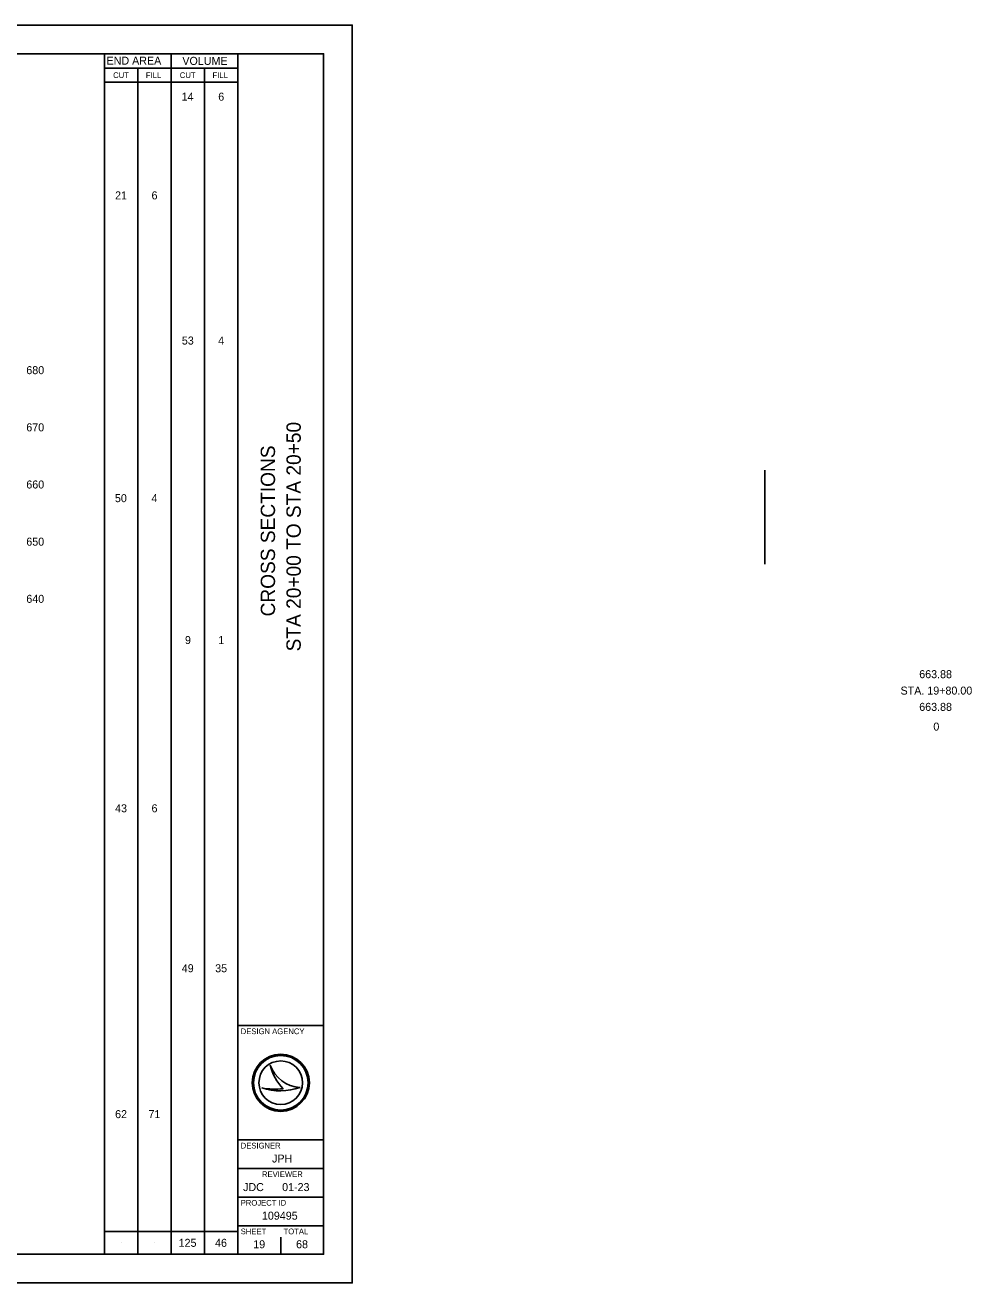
# Model space of a CAD drawing. Extents: x -42 to 262, y 0 to 24.
# Drawn here: x 28.28 to 44.84, y 0 to 22 of the extents above; entities that cross this region are included whole.
import ezdxf

# ---------------------------------------------------------------- set-up
doc = ezdxf.new("R2010")
doc.units = 0
for name, color, linetype in [('DR_X_Ditch', 7, 'Continuous'), ('PV_X_Driveway', 7, 'Continuous'), ('SH_Border', 7, 'Continuous'), ('SH_Cut_Line', 7, 'Continuous'), ('SH_Data', 7, 'Continuous'), ('SH_Text', 7, 'Continuous'), ('TX_P_10', 7, 'Continuous')]:
    doc.layers.add(name, color=color, linetype=linetype)

msp = doc.modelspace()

# ---------------------------------------------------------------- linework, layer by layer
at = {"layer": 'DR_X_Ditch'}
msp.add_line((41.219, 12.57), (41.219, 14.214), dxfattribs=at)
at = {"layer": 'SH_Border'}
for p, q in [((32, 0.5), (32, 21.5)), ((32, 4.5), (33.5, 4.5)), ((32, 2.5), (33.5, 2.5)), ((32, 2), (33.5, 2)), ((32, 1.5), (33.5, 1.5)), ((32, 1), (33.5, 1))]:
    msp.add_line(p, q, dxfattribs=at)
msp.add_lwpolyline([(1.5, 21.5), (33.5, 21.5), (33.5, 0.5), (1.5, 0.5)], close=True, dxfattribs=at)
at = {"layer": 'SH_Cut_Line'}
msp.add_lwpolyline([(0, 0), (34, 0), (34, 22), (0, 22)], close=True, dxfattribs=at)
at = {"layer": 'SH_Data'}
for p, q in [((29.666, 0.5), (29.666, 21.5)), ((30.833, 0.5), (30.833, 21.5)), ((29.666, 21.25), (32, 21.25)), ((30.25, 0.5), (30.25, 21.25)), ((31.417, 0.5), (31.417, 21.25)), ((29.666, 21), (32, 21)), ((32.567, 3.81), (32.567, 3.81)), ((32.417, 3.41), (32.417, 3.41)), ((32.75, 3.5), (32.75, 3.5)), ((33.087, 3.419), (33.087, 3.419)), ((29.666, 0.9), (32, 0.9)), ((29.958, 0.7), (29.958, 0.7)), ((30.542, 0.7), (30.542, 0.7)), ((31.125, 0.7), (31.125, 0.7)), ((31.708, 0.7), (31.708, 0.7)), ((32.375, 0.675), (32.375, 0.675)), ((32.75, 0.5), (32.75, 0.8))]:
    msp.add_line(p, q, dxfattribs=at)
for radius in [0.5, 0.477, 0.477, 0.382]:
    msp.add_circle((32.75, 3.5), radius, dxfattribs=at)
for centre, radius, start, end in [((33.116, 3.998), 0.58, 198.9257, 198.9319), ((33.347, 3.97), 0.796, 191.6379, 191.6421), ((33.116, 3.998), 0.58, 198.9319, 267.1657), ((33.347, 3.97), 0.796, 191.6421, 226.0947), ((32.739, 4.37), 1.013, 251.4576, 290.0832), ((32.648, 4.654), 1.266, 259.4964, 259.4995), ((32.739, 4.37), 1.013, 251.4527, 251.4576), ((32.648, 4.654), 1.266, 259.4995, 276.6672)]:
    msp.add_arc(centre, radius, start, end, dxfattribs=at)

# ---------------------------------------------------------------- texts
at = {"layer": 'PV_X_Driveway'}
msp.add_text('663.88', height=0.14, dxfattribs=at).set_placement((43.917, 10.005))
at = {"layer": 'SH_Data'}
for s, height, p in [('END AREA', 0.14, (29.703, 21.309)), ('VOLUME', 0.14, (31.029, 21.305)), ('CUT', 0.1, (29.819, 21.075)), ('FILL', 0.1, (30.391, 21.075)), ('CUT', 0.1, (30.985, 21.075)), ('FILL', 0.1, (31.557, 21.075)), ('DESIGN AGENCY', 0.1, (32.05, 4.35)), ('DESIGNER', 0.1, (32.05, 2.35)), ('JPH', 0.14, (32.598, 2.105)), ('REVIEWER', 0.1, (32.422, 1.85)), ('JDC', 0.14, (32.091, 1.605)), ('01-23', 0.14, (32.774, 1.605)), ('PROJECT ID', 0.1, (32.05, 1.35)), ('109495', 0.14, (32.421, 1.105)), ('SHEET', 0.1, (32.05, 0.85)), ('TOTAL', 0.1, (32.8, 0.85)), ('19', 0.14, (32.269, 0.605)), ('68', 0.14, (33.018, 0.605))]:
    msp.add_text(s, height=height, dxfattribs=at).set_placement(p)
for s, p in [('STA 20+00 TO STA 20+50', (33.1, 11.046)), ('CROSS SECTIONS', (32.65, 11.657))]:
    msp.add_text(s, height=0.25, rotation=90, dxfattribs=at).set_placement(p)
at = {"layer": 'SH_Text'}
for s, p in [('680', (28.3, 15.895)), ('670', (28.3, 14.895)), ('660', (28.3, 13.895)), ('650', (28.3, 12.895)), ('640', (28.3, 11.895)), ('STA. 19+80.00', (43.59, 10.29)), ('0', (44.164, 9.66))]:
    msp.add_text(s, height=0.14, dxfattribs=at).set_placement(p)
at = {"layer": 'TX_P_10'}
for s, p in [('14', (31.016, 20.679)), ('6', (31.657, 20.679)), ('21', (29.853, 18.952)), ('6', (30.49, 18.952)), ('53', (31.02, 16.413)), ('4', (31.656, 16.413)), ('50', (29.85, 13.656)), ('4', (30.489, 13.656)), ('9', (31.075, 11.174)), ('1', (31.658, 11.174)), ('663.88', (43.917, 10.577)), ('43', (29.853, 8.231)), ('6', (30.49, 8.231)), ('49', (31.019, 5.433)), ('35', (31.603, 5.433)), ('62', (29.853, 2.881)), ('71', (30.436, 2.881)), ('125', (30.964, 0.63)), ('46', (31.601, 0.63))]:
    msp.add_text(s, height=0.14, dxfattribs=at).set_placement(p)

doc.saveas('drawing.dxf')
